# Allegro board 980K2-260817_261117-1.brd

Outline 419.1 x 474.98 mm; copper layers: TOP, L02_GND, L03_DP, L04_GND, L05_DP, L06_GND, L07_VI, L08_GND, L09_VI, L10_GND, L11_VI, L12_GND, L13_VI, L14_GND, L15_5V, L16_5V, L17_C-BIT, L18_C-BIT, L19_GND, L20_VI, L21_GND, L22_VI, L23_GND, L24_VI, L25_GND, L26_VI, L27_GND, L28_DP, L29_GND, L30_DP, L31_GND, BOTTOM. Coordinates in mm from the lower left corner of the outline.

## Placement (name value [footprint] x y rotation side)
BC9  0.1U-50-X-S4-TDK  [C0402]  86.11 107.82 180 bottom
BR5  1K-1-S4  [R0402]  86.11 106.3 0 bottom
BR6  1K-1-S4  [R0402]  86.11 103.5 0 bottom
BR7  0-5-S6  [R0603]  83.44 106.3 180 bottom
BR8  0-5-S4  [R0402]  86.11 105.03 180 bottom
BR9  0-5-S4  [R0402]  86.11 102.24 180 bottom
BU1  AT24C512C-SSHM-T-SOIC8  [SO8_206X127MM]  91.06 105.66 180 bottom
C48  0.01U-100-X7R-S6-MU  [C0603]  147.57 273.87 90 bottom
C49  0.01U-100-X7R-S6-MU  [C0603]  136.27 268.99 270 bottom
C50  0.01U-100-X7R-S6-MU  [C0603]  142.28 268.54 270 bottom
C53  1U-16-X5R-S4-YA  [C0402]  142.24 261.62 270 bottom
C54  2.2U-16-X-S4-MU  [C0402]  136.53 261.62 270 bottom
C58  1U-16-X5R-S4-YA  [C0402]  142.11 257.68 270 bottom
C59  4.7U-100-X-SB-MU  [C1210]  140.59 246.51 270 bottom
C60  0.01U-100-X7R-S6-MU  [C0603]  147.01 259.72 0 bottom
C61  0.01U-100-X7R-S6-MU  [C0603]  156.88 264.78 180 bottom
C62  2.2U-16-X-S4-MU  [C0402]  157.07 259.72 0 bottom
C63  0.01U-100-X7R-S6-MU  [C0603]  157.73 261.82 90 bottom
C64  0.01U-100-X7R-S6-MU  [C0603]  156.88 267.82 180 bottom
C65  0.1U-25-X7R-S4-MU  [C0402]  157.73 271.37 90 bottom
C66  0.1U-25-X7R-S4-MU  [C0402]  152.65 276.61 180 bottom
C67  0.1U-25-X7R-S4-MU  [C0402]  150.24 278.13 180 bottom
C68  0.1U-25-X7R-S4-MU  [C0402]  147.83 282.7 180 bottom
C69  0.01U-100-X7R-S6-MU  [C0603]  151.96 259.72 0 bottom
C70  0.1U-25-X7R-S4-MU  [C0402]  122.8 294.89 180 bottom
C71  0.1U-25-X7R-S4-MU  [C0402]  129.42 294.89 180 bottom
C72  0.1U-25-X7R-S4-MU  [C0402]  158.75 227.33 0 bottom
C73  0.1U-25-X7R-S4-MU  [C0402]  153.67 227.33 0 bottom
C74  0.1U-25-X7R-S4-MU  [C0402]  157.73 273.91 90 bottom
CT1  47U-16-X5R-SB-MU  [C1210]  88.14 153.16 180 bottom
CT2  10U-16-X5R-S8-TY  [C0805]  108.2 164.59 90 bottom
CT3  22U-16-X-S8-MU  [C0805]  110.49 164.59 90 bottom
CT7  47U-16-X5R-SB-MU  [C1210]  88.14 132.84 180 bottom
CT8  10U-16-X5R-S8-TY  [C0805]  110.49 144.27 90 bottom
CT9  22U-16-X-S8-MU  [C0805]  108.2 144.27 90 bottom
F1  C1F8-0.25A-SA  [FUSE_1206_H1P05MM]  88.14 156.72 0 bottom
F2  C1F8-0.25A-SA  [FUSE_1206_H1P05MM]  88.14 136.4 0 bottom
FD1  -  [FD_040_V2]  95.25 123.19 0 top
FD2  -  [FD_040_V2]  323.85 123.19 0 top
FD3  -  [FD_040_V2]  323.85 351.79 0 top
FD4  -  [FD_040_V2]  95.25 351.79 0 top
FD5  -  [FD_040_V2]  323.85 123.19 180 bottom
FD6  -  [FD_040_V2]  95.25 123.19 180 bottom
FD7  -  [FD_040_V2]  95.25 351.79 180 bottom
FD8  -  [FD_040_V2]  323.85 351.79 180 bottom
FD9  -  [FD_040_V2]  19.05 123.19 0 top
FD10  -  [FD_040_V2]  400.05 123.19 0 top
FD11  -  [FD_040_V2]  400.05 351.79 0 top
FD12  -  [FD_040_V2]  19.05 351.79 0 top
FD13  -  [FD_040_V2]  400.05 123.19 180 bottom
FD14  -  [FD_040_V2]  19.05 123.19 180 bottom
FD15  -  [FD_040_V2]  19.05 351.79 180 bottom
FD16  -  [FD_040_V2]  400.05 351.79 180 bottom
K1  UA2-5NJ-A-V3  [RL_NECUA2_5V_V3]  138.43 290.63 270 bottom
K2  G3VM-201DR  [RL_G3VM201DR_200V]  144.15 277.5 0 bottom
K3  G3VM-201DR  [RL_G3VM201DR_200V]  134.49 273.18 90 bottom
K4  G3VM-201DR  [RL_G3VM201DR_200V]  144.15 291.47 0 bottom
K5  G3VM-51UR-5V-VSON4  [RL_G3VM_4P_VSON4]  139.95 268.99 0 bottom
K6  G3VM-51UR-5V-VSON4  [RL_G3VM_4P_VSON4]  139.95 266.19 0 bottom
K7  G3VM-51UR-5V-VSON4  [RL_G3VM_4P_VSON4]  139.95 264.16 0 bottom
K8  G3VM-51UR-5V-VSON4  [RL_G3VM_4P_VSON4]  139.95 261.62 0 bottom
K9  G3VM-51UR-5V-VSON4  [RL_G3VM_4P_VSON4]  134.24 261.62 0 bottom
K10  G3VM-51UR-5V-VSON4  [RL_G3VM_4P_VSON4]  135.38 264.16 0 bottom
K11  G3VM-51UR-5V-VSON4  [RL_G3VM_4P_VSON4]  143.76 257.3 90 bottom
K12  G3VM-51UR-5V-VSON4  [RL_G3VM_4P_VSON4]  143.76 252.48 90 bottom
K13  G3VM-51UR-5V-VSON4  [RL_G3VM_4P_VSON4]  143.76 246.51 90 bottom
K14  G3VM-51UR-5V-VSON4  [RL_G3VM_4P_VSON4]  146.56 252.48 90 bottom
K15  UA2-5NJ-A-V3  [RL_NECUA2_5V_V3]  135.25 242.75 270 bottom
K16  G3VM-51UR-5V-VSON4  [RL_G3VM_4P_VSON4]  146.56 257.3 90 bottom
K17  G3VM-51UR-5V-VSON4  [RL_G3VM_4P_VSON4]  148.72 257.3 90 bottom
K18  G3VM-51UR-5V-VSON4  [RL_G3VM_4P_VSON4]  148.72 252.48 90 bottom
K19  G3VM-51UR-5V-VSON4  [RL_G3VM_4P_VSON4]  151.51 257.3 90 bottom
K20  G3VM-51UR-5V-VSON4  [RL_G3VM_4P_VSON4]  151.51 252.48 90 bottom
K21  G3VM-51UR-5V-VSON4  [RL_G3VM_4P_VSON4]  153.67 257.3 90 bottom
K22  G3VM-51UR-5V-VSON4  [RL_G3VM_4P_VSON4]  153.67 252.48 90 bottom
K23  UA2-5NJ-A-V3  [RL_NECUA2_5V_V3]  152.78 242.75 270 bottom
K24  UA2-5NJ-A-V3  [RL_NECUA2_5V_V3]  161.04 242.75 270 bottom
K25  G3VM-51UR-5V-VSON4  [RL_G3VM_4P_VSON4]  156.97 257.3 90 bottom
K26  G3VM-51UR-5V-VSON4  [RL_G3VM_4P_VSON4]  156.97 252.48 90 bottom
K27  G3VM-51UR-5V-VSON4  [RL_G3VM_4P_VSON4]  160.15 261.37 180 bottom
K28  G3VM-51UR-5V-VSON4  [RL_G3VM_4P_VSON4]  164.72 261.37 180 bottom
K29  G3VM-51UR-5V-VSON4  [RL_G3VM_4P_VSON4]  169.29 261.37 180 bottom
K30  G3VM-51UR-5V-VSON4  [RL_G3VM_4P_VSON4]  160.15 265.18 180 bottom
K31  G3VM-51UR-5V-VSON4  [RL_G3VM_4P_VSON4]  164.72 265.18 180 bottom
K32  G3VM-51UR-5V-VSON4  [RL_G3VM_4P_VSON4]  169.29 265.18 180 bottom
K33  G3VM-51UR-5V-VSON4  [RL_G3VM_4P_VSON4]  160.15 268.22 180 bottom
K34  G3VM-51UR-5V-VSON4  [RL_G3VM_4P_VSON4]  164.72 268.22 180 bottom
K35  G3VM-51UR-5V-VSON4  [RL_G3VM_4P_VSON4]  169.29 268.22 180 bottom
K36  G3VM-51UR-5V-VSON4  [RL_G3VM_4P_VSON4]  160.15 271.27 180 bottom
K37  G3VM-51UR-5V-VSON4  [RL_G3VM_4P_VSON4]  164.72 271.27 180 bottom
K38  G3VM-51UR-5V-VSON4  [RL_G3VM_4P_VSON4]  160.15 273.81 180 bottom
K39  G3VM-51UR-5V-VSON4  [RL_G3VM_4P_VSON4]  164.72 273.81 180 bottom
K40  G3VM-51UR-5V-VSON4  [RL_G3VM_4P_VSON4]  155.58 273.05 270 bottom
K41  G3VM-51UR-5V-VSON4  [RL_G3VM_4P_VSON4]  155.58 277.62 270 bottom
K42  G3VM-51UR-5V-VSON4  [RL_G3VM_4P_VSON4]  155.58 282.19 270 bottom
K43  G3VM-51UR-5V-VSON4  [RL_G3VM_4P_VSON4]  152.65 273.05 270 bottom
K44  G3VM-51UR-5V-VSON4  [RL_G3VM_4P_VSON4]  152.65 278.89 270 bottom
K45  G3VM-51UR-5V-VSON4  [RL_G3VM_4P_VSON4]  152.65 283.46 270 bottom
K46  G3VM-51UR-5V-VSON4  [RL_G3VM_4P_VSON4]  150.24 274.57 270 bottom
K47  G3VM-51UR-5V-VSON4  [RL_G3VM_4P_VSON4]  150.24 280.42 270 bottom
K48  G3VM-51UR-5V-VSON4  [RL_G3VM_4P_VSON4]  150.24 284.99 270 bottom
K49  G3VM-51UR-5V-VSON4  [RL_G3VM_4P_VSON4]  147.83 284.99 270 bottom
K50  G3VM-51UR-5V-VSON4  [RL_G3VM_4P_VSON4]  147.83 279.15 270 bottom
K51  G3VM-51UR-5V-VSON4  [RL_G3VM_4P_VSON4]  148.72 246.51 270 bottom
K52  G3VM-51UR-5V-VSON4  [RL_G3VM_4P_VSON4]  148.72 241.17 90 bottom
K53  G3VM-51UR-5V-VSON4  [RL_G3VM_4P_VSON4]  156.97 246.51 270 bottom
K54  G3VM-51UR-5V-VSON4  [RL_G3VM_4P_VSON4]  156.97 241.17 90 bottom
K55  G3VM-51UR-5V-VSON4  [RL_G3VM_4P_VSON4]  123.44 292.35 0 bottom
K56  G3VM-201DR  [RL_G3VM201DR_200V]  128.4 288.67 90 bottom
K57  G3VM-51UR-5V-VSON4  [RL_G3VM_4P_VSON4]  158.12 234.57 270 bottom
K58  G3VM-51UR-5V-VSON4  [RL_G3VM_4P_VSON4]  156.08 234.57 270 bottom
K59  G3VM-51UR-5V-VSON4  [RL_G3VM_4P_VSON4]  153.04 234.57 270 bottom
K60  G3VM-51UR-5V-VSON4  [RL_G3VM_4P_VSON4]  151 234.57 270 bottom
K61  G3VM-51UR-5V-VSON4  [RL_G3VM_4P_VSON4]  130.05 292.35 0 bottom
LD1  LDG-2-S6  [LED_0603]  88.91 165.19 0 top
LD3  LDG-2-S6  [LED_0603]  88.91 144.87 0 top
LT1  L10U-16A-S16.5X15.5-PU  [IND_16P5X15P5MM]  98.93 156.59 0 bottom
LT3  L10U-16A-S16.5X15.5-PU  [IND_16P5X15P5MM]  98.93 136.27 0 bottom
M1  PG_LTXDX_F_X1_OUTLINE_TD_V2  [PG_LTXDX_F_X1_OUTLINE_TD_COHU]  209.55 237.49 0 top
NOREF  -  []  264.16 196.43 90 top
NOREF#2  -  []  174.43 232.23 0 top
NOREF#3  -  []  228.81 250.88 90 top
NOREF#4  -  []  248.54 204.45 90 top
NOREF#5  -  []  281.75 212.22 0 top
NOREF#6  -  []  227.3 280.35 0 top
NOREF#7  -  []  283.84 274.21 0 top
NOREF#8  -  []  262.81 186.81 0 top
NOREF#9  -  []  196.8 285.06 90 top
NOREF#10  -  []  173.62 229.09 90 top
NOREF#11  -  []  208.42 264.78 90 top
NOREF#12  -  []  151.91 251.6 90 top
NOREF#13  -  []  171.65 233.3 90 top
NOREF#14  -  []  134.43 232.23 0 top
NOREF#15  -  []  153.18 282.26 90 top
NOREF#16  -  []  159.72 214.65 90 top
NOREF#17  -  []  204.95 207.27 90 top
NOREF#18  -  []  155.05 218.82 0 top
NOREF#19  -  []  106.83 127.87 90 top
NOREF#20  -  []  227.8 269.99 0 top
NOREF#21  -  []  143.61 396.29 0 top
NOREF#22  -  []  274.33 264.33 90 top
NOREF#23  -  []  226.01 244.91 90 top
NOREF#24  -  []  199.27 265.58 0 top
NOREF#25  -  []  271.95 238.07 0 top
NOREF#26  -  []  274.07 256.43 90 top
NOREF#27  -  []  159.27 273.41 90 top
NOREF#28  -  []  90.49 457.2 0 top
NOREF#29  -  []  220.83 265.79 90 top
NOREF#30  -  []  273.56 233.37 90 top
NOREF#31  -  []  270.77 223.79 90 top
NOREF#32  -  []  199.4 213.09 90 top
NOREF#33  -  []  218.35 207.01 0 top
NOREF#34  -  []  279.27 261.77 0 top
NOREF#35  -  []  148.32 198.18 0 top
NOREF#36  -  []  231.11 260.17 90 top
NOREF#37  -  []  261.55 209.94 90 top
NOREF#38  -  []  122.85 281.02 0 top
NOREF#39  -  []  178.85 181.15 90 top
NOREF#40  -  []  232.13 220.09 0 top
NOREF#41  -  []  272.72 257.6 0 top
NOREF#42  -  []  166.32 212.22 0 top
NOREF#43  -  []  224.16 191.6 90 top
NOREF#44  -  []  195.68 233.69 90 top
NOREF#45  -  []  232.25 218.02 90 top
NOREF#46  -  []  159.27 201.77 0 top
NOREF#47  -  []  152.46 252.5 90 top
NOREF#48  -  []  179.72 213.6 90 top
NOREF#49  -  []  235.17 212.18 0 top
NOREF#50  -  []  277.25 256.75 0 top
NOREF#51  -  []  200.23 236.17 90 top
NOREF#52  -  []  234.33 204.33 90 top
NOREF#53  -  []  124.61 294.24 90 top
NOREF#54  -  []  232.66 226.35 90 top
NOREF#55  -  []  170.02 214.45 0 top
NOREF#56  -  []  223.49 257.85 90 top
NOREF#57  -  []  265.41 286.99 90 top
NOREF#58  -  []  146.28 193.03 90 top
NOREF#59  -  []  193.27 253.35 0 top
NOREF#60  -  []  162.85 297.22 0 top
NOREF#61  -  []  151.53 173.37 90 top
NOREF#62  -  []  239.27 274.21 0 top
NOREF#63  -  []  257.29 247.78 0 top
NOREF#64  -  []  176.38 264.09 90 top
NOREF#65  -  []  195.05 214.25 0 top
NOREF#66  -  []  236.81 232.54 0 top
NOREF#67  -  []  152.13 274.25 0 top
NOREF#68  -  []  276.38 241.15 90 top
NOREF#69  -  []  229.84 273.7 90 top
NOREF#70  -  []  236.1 271.85 90 top
NOREF#71  -  []  151.95 238.07 0 top
NOREF#72  -  []  243.92 229.94 0 top
NOREF#73  -  []  178.95 266.12 0 top
NOREF#74  -  []  276.79 171.3 0 top
NOREF#75  -  []  201.75 266.13 0 top
NOREF#76  -  []  243.97 260.64 90 top
NOREF#77  -  []  238.91 232.21 90 top
NOREF#78  -  []  219.08 205.79 0 top
NOREF#79  -  []  187.43 224.11 90 top
NOREF#80  -  []  139.08 203.76 0 top
NOREF#81  -  []  286.32 272.22 0 top
NOREF#82  -  []  276.61 233.37 90 top
NOREF#83  -  []  195.68 233.69 0 top
NOREF#84  -  []  244.44 292.28 90 top
NOREF#85  -  []  270.97 190.88 90 top
NOREF#86  -  []  178.35 207.01 0 top
NOREF#87  -  []  239.4 262.09 0 top
NOREF#88  -  []  152.25 212.18 0 top
NOREF#89  -  []  178.35 269.04 0 top
NOREF#90  -  []  157.04 244.35 0 top
NOREF#91  -  []  149.12 256.43 90 top
NOREF#92  -  []  236.1 220.99 90 top
NOREF#93  -  []  248.42 261.77 0 top
NOREF#94  -  []  279.4 205.9 0 top
NOREF#95  -  []  222.81 246.81 0 top
NOREF#96  -  []  279.72 214.65 90 top
NOREF#97  -  []  215.24 201.55 90 top
NOREF#98  -  []  235.68 173.69 90 top
NOREF#99  -  []  144.71 241.71 90 top
NOREF#100  -  []  216.63 232.23 0 top
NOREF#101  -  []  169.52 267.27 90 top
NOREF#102  -  []  220.95 264.09 90 top
NOREF#103  -  []  243.84 267.82 90 top
NOREF#104  -  []  272.63 173.69 90 top
NOREF#105  -  []  151.11 258.18 0 top
NOREF#106  -  []  294.09 264.23 90 top
NOREF#107  -  []  157.18 176.17 90 top
NOREF#108  -  []  175.84 202.57 90 top
NOREF#109  -  []  192.25 278.02 90 top
NOREF#110  -  []  227.8 264.99 90 top
NOREF#111  -  []  208.42 267.82 90 top
NOREF#112  -  []  156.84 167.33 0 top
NOREF#113  -  []  288.42 264.78 90 top
NOREF#114  -  []  264.16 185.63 90 top
NOREF#115  -  []  152.63 233.69 0 top
NOREF#116  -  []  261.59 308.11 0 top
NOREF#117  -  []  283.97 207.5 90 top
NOREF#118  -  []  181.55 269.94 90 top
NOREF#119  -  []  279.06 238.07 0 top
NOREF#120  -  []  263.49 193.03 90 top
NOREF#121  -  []  232.87 248.11 90 top
NOREF#122  -  []  240.13 456.29 90 top
NOREF#123  -  []  235.15 236.17 90 top
NOREF#124  -  []  174.04 210.63 90 top
NOREF#125  -  []  148.32 258.18 0 top
NOREF#126  -  []  233.27 258.18 0 top
NOREF#127  -  []  266.69 283.04 90 top
NOREF#128  -  []  223.49 193.03 90 top
NOREF#129  -  []  208.42 208.62 0 top
NOREF#130  -  []  136.28 307.18 0 top
NOREF#131  -  []  199.4 264.45 90 top
NOREF#132  -  []  123.92 229.94 0 top
NOREF#133  -  []  88.44 105.03 90 top
NOREF#134  -  []  88.14 130.81 90 top
NOREF#135  -  []  173.24 261.55 0 top
NOREF#136  -  []  275.17 212.18 90 top
NOREF#137  -  []  209.49 220.89 0 top
NOREF#138  -  []  203.97 213.09 90 top
NOREF#139  -  []  281.75 269.17 0 top
NOREF#140  -  []  181.6 308.11 0 top
NOREF#141  -  []  210.89 209.17 0 top
NOREF#142  -  []  286.32 262.32 0 top
NOREF#143  -  []  191.76 227.33 0 top
NOREF#144  -  []  198.64 173.37 90 top
NOREF#145  -  []  155.05 283.39 0 top
NOREF#146  -  []  173.34 17.15 0 top
NOREF#147  -  []  261.55 269.94 90 top
NOREF#148  -  []  220.83 205.79 90 top
NOREF#149  -  []  153.03 232.1 0 top
NOREF#150  -  []  146.17 286.14 90 top
NOREF#151  -  []  249.17 231.95 0 top
NOREF#152  -  []  155.68 233.69 90 top
NOREF#153  -  []  199.27 268.62 0 top
NOREF#154  -  []  196.57 245.63 0 top
NOREF#155  -  []  221.55 262.57 90 top
NOREF#156  -  []  151.24 197.85 90 top
NOREF#157  -  []  149.24 185.31 90 top
NOREF#158  -  []  221.59 294.14 0 top
NOREF#159  -  []  288.42 207.82 90 top
NOREF#160  -  []  163.97 268.95 0 top
NOREF#161  -  []  268.99 196.75 0 top
NOREF#162  -  []  151.91 256.43 90 top
NOREF#163  -  []  145.61 192.78 0 top
NOREF#164  -  []  279.27 273.41 90 top
NOREF#165  -  []  231.18 179.15 0 top
NOREF#166  -  []  188.32 185.63 90 top
NOREF#167  -  []  276.1 280.99 90 top
NOREF#168  -  []  154.07 191.6 90 top
NOREF#169  -  []  211.14 458.49 0 top
NOREF#170  -  []  192.25 272.17 90 top
NOREF#171  -  []  148.32 182.05 0 top
NOREF#172  -  []  232.63 173.69 90 top
NOREF#173  -  []  154.62 252.5 90 top
NOREF#174  -  []  151.24 193.03 90 top
NOREF#175  -  []  286.32 269.17 0 top
NOREF#176  -  []  199.27 274.21 0 top
NOREF#177  -  []  203.84 261.77 0 top
NOREF#178  -  []  139.55 234.49 0 top
NOREF#179  -  []  210.89 266.13 0 top
NOREF#180  -  []  260.83 268.59 90 top
NOREF#181  -  []  150.41 228.7 90 top
NOREF#182  -  []  196.84 167.33 0 top
NOREF#183  -  []  281.75 209.17 0 top
NOREF#184  -  []  251.05 245.49 90 top
NOREF#185  -  []  258.35 271.84 0 top
NOREF#186  -  []  214.51 263.76 0 top
NOREF#187  -  []  187.8 209.99 0 top
NOREF#188  -  []  216.55 254.49 90 top
NOREF#189  -  []  236.02 192.78 0 top
NOREF#190  -  []  266.96 196.43 90 top
NOREF#191  -  []  237.25 196.75 0 top
NOREF#192  -  []  185.41 273.02 90 top
NOREF#193  -  []  159.72 223.79 90 top
NOREF#194  -  []  199.27 261.77 0 top
NOREF#195  -  []  149.67 190.01 0 top
NOREF#196  -  []  231.79 191.93 0 top
NOREF#197  -  []  159.06 178.07 0 top
NOREF#198  -  []  159.65 272.56 0 top
NOREF#199  -  []  196.52 216.55 0 top
NOREF#200  -  []  156.1 276.42 90 top
NOREF#201  -  []  236.02 197.6 0 top
NOREF#202  -  []  281.75 266.13 0 top
NOREF#203  -  []  136.55 220.49 0 top
NOREF#204  -  []  237.18 176.17 90 top
NOREF#205  -  []  181.6 234.15 0 top
NOREF#206  -  []  276.1 276.42 90 top
NOREF#207  -  []  275.56 175.77 0 top
NOREF#208  -  []  275.96 168.6 90 top
NOREF#209  -  []  226.96 251.6 90 top
NOREF#210  -  []  199.72 274.65 90 top
NOREF#211  -  []  232.25 272.17 90 top
NOREF#212  -  []  279.44 239.15 0 top
NOREF#213  -  []  124.61 234.89 90 top
NOREF#214  -  []  293.99 17.15 90 top
NOREF#215  -  []  196.38 241.15 90 top
NOREF#216  -  []  129.44 260.67 90 top
NOREF#217  -  []  191.11 253.35 0 top
NOREF#218  -  []  279.27 213.41 90 top
NOREF#219  -  []  243.84 274.21 0 top
NOREF#220  -  []  154.84 18.69 90 top
NOREF#221  -  []  283.97 212 0 top
NOREF#222  -  []  161.75 214.76 0 top
NOREF#223  -  []  228.32 245.63 90 top
NOREF#224  -  []  276.57 185.63 90 top
NOREF#225  -  []  220.95 266.12 90 top
NOREF#226  -  []  148.44 193.03 90 top
NOREF#227  -  []  214.43 232.23 0 top
NOREF#228  -  []  197.04 184.35 0 top
NOREF#229  -  []  178.85 241.15 90 top
NOREF#230  -  []  231.91 191.6 90 top
NOREF#231  -  []  236.79 171.3 0 top
NOREF#232  -  []  153.56 233.37 90 top
NOREF#233  -  []  284.64 241.15 90 top
NOREF#234  -  []  157.25 240.62 0 top
NOREF#235  -  []  244.32 231.95 90 top
NOREF#236  -  []  279.27 214.21 0 top
NOREF#237  -  []  211.05 229.49 0 top
NOREF#238  -  []  149.55 318.49 0 top
NOREF#239  -  []  180.83 265.79 90 top
NOREF#240  -  []  271.71 231.3 0 top
NOREF#241  -  []  189.12 191.6 90 top
NOREF#242  -  []  169.52 212.86 90 top
NOREF#243  -  []  233.76 255.7 90 top
NOREF#244  -  []  147.8 264.99 90 top
NOREF#245  -  []  237.37 196.43 90 top
NOREF#246  -  []  275.92 250.88 90 top
NOREF#247  -  []  267.77 181.47 0 top
NOREF#248  -  []  143.36 247.38 0 top
NOREF#249  -  []  159.4 273.09 90 top
NOREF#250  -  []  147.45 209.24 0 top
NOREF#251  -  []  199.27 207.82 90 top
NOREF#252  -  []  196.1 280.99 90 top
NOREF#253  -  []  241.44 244.35 0 top
NOREF#254  -  []  256.55 254.49 90 top
NOREF#255  -  []  168.54 200.64 90 top
NOREF#256  -  []  276.57 198.18 0 top
NOREF#257  -  []  118.64 291.4 90 top
NOREF#258  -  []  181.03 267.69 90 top
NOREF#259  -  []  160.23 236.17 90 top
NOREF#260  -  []  197.74 226.35 90 top
NOREF#261  -  []  183.36 258.18 0 top
NOREF#262  -  []  194.39 286.59 90 top
NOREF#263  -  []  200.23 176.17 90 top
NOREF#264  -  []  236.8 220.49 90 top
NOREF#265  -  []  279.72 279.22 90 top
NOREF#266  -  []  279.4 270.55 90 top
NOREF#267  -  []  163.97 200.64 90 top
NOREF#268  -  []  149.55 188.99 90 top
NOREF#269  -  []  213.24 201.55 0 top
NOREF#270  -  []  276.81 172.54 0 top
NOREF#271  -  []  156.1 216.42 90 top
NOREF#272  -  []  186.16 193.35 0 top
NOREF#273  -  []  178.97 18.69 90 top
NOREF#274  -  []  256.38 204.09 90 top
NOREF#275  -  []  270.15 206.89 90 top
NOREF#276  -  []  88.16 144.87 0 top
NOREF#277  -  []  123.91 295.42 90 top
NOREF#278  -  []  232.25 278.02 0 top
NOREF#279  -  []  261.03 267.69 90 top
NOREF#280  -  []  187.9 265.84 90 top
NOREF#281  -  []  168.45 235.2 0 top
NOREF#282  -  []  272.13 280.09 0 top
NOREF#283  -  []  159.27 211.67 0 top
NOREF#284  -  []  241.12 248.11 90 top
NOREF#285  -  []  201.41 167.9 90 top
NOREF#286  -  []  261.55 202.57 90 top
NOREF#287  -  []  259.39 16.49 0 top
NOREF#288  -  []  155.05 214.25 0 top
NOREF#289  -  []  288.54 267.5 90 top
NOREF#290  -  []  88.16 165.19 0 top
NOREF#291  -  []  280.23 236.17 90 top
NOREF#292  -  []  229.84 273.7 0 top
NOREF#293  -  []  199.65 212.56 0 top
NOREF#294  -  []  85.59 135.25 90 top
NOREF#295  -  []  216.63 292.23 0 top
NOREF#296  -  []  267.43 218.27 90 top
NOREF#297  -  []  209.52 260.42 90 top
NOREF#298  -  []  174.43 292.23 0 top
NOREF#299  -  []  188.32 198.18 0 top
NOREF#300  -  []  203.84 267.82 90 top
NOREF#301  -  []  289.52 272.86 90 top
NOREF#302  -  []  229.72 215.77 0 top
NOREF#303  -  []  279.27 208.62 0 top
NOREF#304  -  []  221.55 202.57 90 top
NOREF#305  -  []  163.84 214.21 0 top
NOREF#306  -  []  233.94 256.75 0 top
NOREF#307  -  []  231.91 196.43 90 top
NOREF#308  -  []  270.98 184.35 0 top
NOREF#309  -  []  151.79 196.75 0 top
NOREF#310  -  []  281.75 214.76 0 top
NOREF#311  -  []  318.12 17.15 0 top
NOREF#312  -  []  226.43 236.47 90 top
NOREF#313  -  []  156.52 216.55 0 top
NOREF#314  -  []  259.08 268.59 0 top
NOREF#315  -  []  188.32 253.35 0 top
NOREF#316  -  []  199.27 271.67 0 top
NOREF#317  -  []  143.36 187.38 0 top
NOREF#318  -  []  152.72 197.6 0 top
NOREF#319  -  []  148.35 217.95 90 top
NOREF#320  -  []  149.12 180.3 90 top
NOREF#321  -  []  270.56 257.6 0 top
NOREF#322  -  []  220.59 184.98 90 top
NOREF#323  -  []  226.7 237.02 90 top
NOREF#324  -  []  255.65 184.35 0 top
NOREF#325  -  []  193.56 173.37 90 top
NOREF#326  -  []  268.35 283.79 90 top
NOREF#327  -  []  147.8 269.99 0 top
NOREF#328  -  []  133.62 229.09 90 top
NOREF#329  -  []  151.11 198.18 0 top
NOREF#330  -  []  163.84 271.67 0 top
NOREF#331  -  []  198.64 233.37 90 top
NOREF#332  -  []  208.94 221.73 0 top
NOREF#333  -  []  211.05 185.49 90 top
NOREF#334  -  []  181.94 389.27 90 top
NOREF#335  -  []  139.55 240.49 90 top
NOREF#336  -  []  194.07 191.6 90 top
NOREF#337  -  []  238.11 172.1 0 top
NOREF#338  -  []  249.52 267.27 90 top
NOREF#339  -  []  269.72 221.62 0 top
NOREF#340  -  []  264.26 396.29 0 top
NOREF#341  -  []  151.98 226.59 90 top
NOREF#342  -  []  243.97 213.09 90 top
NOREF#343  -  []  254.09 200.42 90 top
NOREF#344  -  []  157.04 244.35 0 top
NOREF#345  -  []  146.7 237.02 90 top
NOREF#346  -  []  157.92 236.37 90 top
NOREF#347  -  []  180.43 284.38 90 top
NOREF#348  -  []  268.44 193.03 90 top
NOREF#349  -  []  196.57 198.18 0 top
NOREF#350  -  []  163.97 204.45 90 top
NOREF#351  -  []  195.15 176.17 90 top
NOREF#352  -  []  149.84 284.11 90 top
NOREF#353  -  []  195.92 195.7 90 top
NOREF#354  -  []  179.08 208.59 0 top
NOREF#355  -  []  191.85 18.69 0 top
NOREF#356  -  []  266.16 253.35 0 top
NOREF#357  -  []  236.02 252.78 0 top
NOREF#358  -  []  123.4 281.8 0 top
NOREF#359  -  []  266.69 297.01 90 top
NOREF#360  -  []  151.71 231.3 0 top
NOREF#361  -  []  271.98 280.75 90 top
NOREF#362  -  []  277.04 244.35 0 top
NOREF#363  -  []  268.32 253.35 0 top
NOREF#364  -  []  199.27 200.97 90 top
NOREF#365  -  []  145.42 213.02 90 top
NOREF#366  -  []  276.8 220.49 90 top
NOREF#367  -  []  180.95 204.09 90 top
NOREF#368  -  []  135.15 260.67 0 top
NOREF#369  -  []  274.78 236.5 90 top
NOREF#370  -  []  164.32 291.95 90 top
NOREF#371  -  []  190.97 239.57 90 top
NOREF#372  -  []  249.05 292.28 0 top
NOREF#373  -  []  189.72 286.19 0 top
NOREF#374  -  []  267.45 269.24 0 top
NOREF#375  -  []  189.84 219.54 0 top
NOREF#376  -  []  227.03 231.4 0 top
NOREF#377  -  []  233.18 211.85 90 top
NOREF#378  -  []  91.03 148.19 0 top
NOREF#379  -  []  149.84 219.54 0 top
NOREF#380  -  []  147.03 231.4 0 top
NOREF#381  -  []  148.32 245.63 90 top
NOREF#382  -  []  257.29 187.78 0 top
NOREF#383  -  []  190.56 192.78 0 top
NOREF#384  -  []  224.04 251.93 0 top
NOREF#385  -  []  235.96 228.6 90 top
NOREF#386  -  []  231.95 178.07 0 top
NOREF#387  -  []  270.98 244.35 0 top
NOREF#388  -  []  136.83 227.03 0 top
NOREF#389  -  []  159.24 184.35 0 top
NOREF#390  -  []  236.1 216.42 90 top
NOREF#391  -  []  243.84 270.87 90 top
NOREF#392  -  []  152.63 233.69 90 top
NOREF#393  -  []  247.04 299.09 0 top
NOREF#394  -  []  269.12 180.3 90 top
NOREF#395  -  []  91.03 127.87 0 top
NOREF#396  -  []  290.89 209.17 0 top
NOREF#397  -  []  237.5 185.31 90 top
NOREF#398  -  []  146.16 258.18 0 top
NOREF#399  -  []  186.01 255.7 90 top
NOREF#400  -  []  156.1 280.99 90 top
NOREF#401  -  []  220.83 261.22 90 top
NOREF#402  -  []  155.96 228.6 90 top
NOREF#403  -  []  241.75 212.22 0 top
NOREF#404  -  []  149.29 279.37 0 top
NOREF#405  -  []  128.45 235.2 0 top
NOREF#406  -  []  149.55 248.99 90 top
NOREF#407  -  []  264.16 191.6 90 top
NOREF#408  -  []  253.64 299.09 0 top
NOREF#409  -  []  174.51 263.76 0 top
NOREF#410  -  []  201.44 184.35 0 top
NOREF#411  -  []  191.91 196.43 90 top
NOREF#412  -  []  228.35 277.95 90 top
NOREF#413  -  []  239.4 205.9 0 top
NOREF#414  -  []  248.42 267.82 90 top
NOREF#415  -  []  279.27 210.87 90 top
NOREF#416  -  []  231.91 251.6 90 top
NOREF#417  -  []  228.44 241.72 90 top
NOREF#418  -  []  187.77 192.78 0 top
NOREF#419  -  []  183.36 247.38 0 top
NOREF#420  -  []  196.5 392.33 90 top
NOREF#421  -  []  283.97 262.09 0 top
NOREF#422  -  []  203.97 265.9 0 top
NOREF#423  -  []  136.5 285.91 0 top
NOREF#424  -  []  174.38 264.09 0 top
NOREF#425  -  []  268.35 223.79 90 top
NOREF#426  -  []  224.04 256.75 0 top
NOREF#427  -  []  264.16 245.63 90 top
NOREF#428  -  []  192.72 257.6 0 top
NOREF#429  -  []  239.06 238.07 0 top
NOREF#430  -  []  231.79 256.75 0 top
NOREF#431  -  []  106.83 148.19 90 top
NOREF#432  -  []  288.54 260.64 90 top
NOREF#433  -  []  208.54 262.09 0 top
NOREF#434  -  []  156.57 185.63 0 top
NOREF#435  -  []  193.18 271.85 90 top
NOREF#436  -  []  223.36 187.38 0 top
NOREF#437  -  []  204.95 270.32 90 top
NOREF#438  -  []  279.4 274.54 0 top
NOREF#439  -  []  243.97 212 0 top
NOREF#440  -  []  245.73 17.15 90 top
NOREF#441  -  []  187.9 205.84 90 top
NOREF#442  -  []  239.27 273.41 90 top
NOREF#443  -  []  270.6 173.69 0 top
NOREF#444  -  []  197.04 244.35 0 top
NOREF#445  -  []  187.03 171.4 0 top
NOREF#446  -  []  180.83 208.59 90 top
NOREF#447  -  []  221.85 246.47 0 top
NOREF#448  -  []  288.39 456.29 0 top
NOREF#449  -  []  201.75 274.76 0 top
NOREF#450  -  []  283.84 200.97 90 top
NOREF#451  -  []  159.27 213.41 90 top
NOREF#452  -  []  275.05 223.39 0 top
NOREF#453  -  []  260.95 204.09 90 top
NOREF#454  -  []  206.32 206.13 0 top
NOREF#455  -  []  163.97 214.54 0 top
NOREF#456  -  []  269.55 188.99 90 top
NOREF#457  -  []  226.96 196.43 90 top
NOREF#458  -  []  226.43 296.46 90 top
NOREF#459  -  []  164.61 294.24 90 top
NOREF#460  -  []  195.92 250.88 90 top
NOREF#461  -  []  227.3 286.19 0 top
NOREF#462  -  []  151.95 178.07 0 top
NOREF#463  -  []  236.7 197.85 90 top
NOREF#464  -  []  100.95 17.15 90 top
NOREF#465  -  []  237.37 240.3 90 top
NOREF#466  -  []  228.32 198.18 0 top
NOREF#467  -  []  208.54 204.45 90 top
NOREF#468  -  []  242.2 238.35 0 top
NOREF#469  -  []  211.25 184.35 0 top
NOREF#470  -  []  199.72 219.22 90 top
NOREF#471  -  []  141.6 234.15 0 top
NOREF#472  -  []  211.21 234.24 90 top
NOREF#473  -  []  270.86 82.65 0 top
NOREF#474  -  []  148.32 242.05 0 top
NOREF#475  -  []  246.32 206.13 0 top
NOREF#476  -  []  271.95 178.07 0 top
NOREF#477  -  []  253.64 239.09 0 top
NOREF#478  -  []  142.88 213.02 0 top
NOREF#479  -  []  150.77 283.79 90 top
NOREF#480  -  []  228.35 223.79 90 top
NOREF#481  -  []  178.83 232.23 0 top
NOREF#482  -  []  199.44 239.15 0 top
NOREF#483  -  []  276.81 232.54 0 top
NOREF#484  -  []  218.35 204.47 0 top
NOREF#485  -  []  271.19 288.49 0 top
NOREF#486  -  []  188.78 228.49 0 top
NOREF#487  -  []  166.32 272.22 0 top
NOREF#488  -  []  232.63 232.86 0 top
NOREF#489  -  []  237.71 172.86 0 top
NOREF#490  -  []  271.98 226.59 90 top
NOREF#491  -  []  176.55 220.49 0 top
NOREF#492  -  []  266.16 198.18 0 top
NOREF#493  -  []  283.97 214.54 0 top
NOREF#494  -  []  235.05 278.82 0 top
NOREF#495  -  []  271.11 253.35 0 top
NOREF#496  -  []  184.16 191.6 90 top
NOREF#497  -  []  192.25 218.02 90 top
NOREF#498  -  []  276.54 227 0 top
NOREF#499  -  []  186.83 256.75 0 top
NOREF#500  -  []  271.98 220.75 90 top
NOREF#501  -  []  161.75 274.76 0 top
NOREF#502  -  []  187.3 286.19 0 top
NOREF#503  -  []  148.78 244.35 0 top
NOREF#504  -  []  134.51 203.76 0 top
NOREF#505  -  []  152.25 278.02 0 top
NOREF#506  -  []  193.03 232.1 0 top
NOREF#507  -  []  234.78 236.5 90 top
NOREF#508  -  []  156.7 241.72 90 top
NOREF#509  -  []  274.78 176.5 90 top
NOREF#510  -  []  140.95 208.91 90 top
NOREF#511  -  []  146.7 223.05 90 top
NOREF#512  -  []  186.16 258.18 0 top
NOREF#513  -  []  191.91 191.6 90 top
NOREF#514  -  []  189.72 215.77 0 top
NOREF#515  -  []  283.84 265.58 0 top
NOREF#516  -  []  138.35 207.01 0 top
NOREF#517  -  []  196.52 225.69 0 top
NOREF#518  -  []  237.37 251.6 90 top
NOREF#519  -  []  157.25 256.75 0 top
NOREF#520  -  []  168.45 295.2 0 top
NOREF#521  -  []  156.79 231.3 0 top
NOREF#522  -  []  186.16 260.17 90 top
NOREF#523  -  []  196.7 241.72 90 top
NOREF#524  -  []  262.81 246.81 0 top
NOREF#525  -  []  204.61 234.89 90 top
NOREF#526  -  []  131.05 229.49 0 top
NOREF#527  -  []  264.04 196.75 0 top
NOREF#528  -  []  237.04 184.35 0 top
NOREF#529  -  []  232.25 212.18 90 top
NOREF#530  -  []  233.39 193.03 90 top
NOREF#531  -  []  236.57 242.05 0 top
NOREF#532  -  []  269.72 286.19 0 top
NOREF#533  -  []  275.05 274.25 0 top
NOREF#534  -  []  164.44 292.28 90 top
NOREF#535  -  []  273.18 184.35 0 top
NOREF#536  -  []  264.26 456.29 0 top
NOREF#537  -  []  243.84 208.62 0 top
NOREF#538  -  []  267.03 231.4 0 top
NOREF#539  -  []  199.4 207.5 90 top
NOREF#540  -  []  233.03 172.1 0 top
NOREF#541  -  []  218.95 266.12 0 top
NOREF#542  -  []  153.39 193.03 90 top
NOREF#543  -  []  182.87 213.02 0 top
NOREF#544  -  []  188.99 180.62 0 top
NOREF#545  -  []  193.27 258.18 0 top
NOREF#546  -  []  197.92 190.01 0 top
NOREF#547  -  []  239.27 210.87 90 top
NOREF#548  -  []  168.42 204.78 90 top
NOREF#549  -  []  275.17 272.17 90 top
NOREF#550  -  []  166.32 206.13 0 top
NOREF#551  -  []  202.26 236.17 90 top
NOREF#552  -  []  237.37 180.3 90 top
NOREF#553  -  []  265.09 197.49 90 top
NOREF#554  -  []  202.85 297.22 0 top
NOREF#555  -  []  222.6 82.65 0 top
NOREF#556  -  []  312.52 456.29 0 top
NOREF#557  -  []  232.72 257.6 0 top
NOREF#558  -  []  189.84 213.7 0 top
NOREF#559  -  []  191.79 251.93 0 top
NOREF#560  -  []  252.55 250.49 90 top
NOREF#561  -  []  276.1 271.85 90 top
NOREF#562  -  []  244.95 270.32 90 top
NOREF#563  -  []  196.1 271.85 90 top
NOREF#564  -  []  151.73 232.54 0 top
NOREF#565  -  []  270.88 228.6 90 top
NOREF#566  -  []  174.51 203.76 0 top
NOREF#567  -  []  196.02 181.47 0 top
NOREF#568  -  []  192.63 172.86 0 top
NOREF#569  -  []  208.42 268.62 0 top
NOREF#570  -  []  278.11 172.1 0 top
NOREF#571  -  []  262.03 289.03 90 top
NOREF#572  -  []  178.35 267.01 0 top
NOREF#573  -  []  230.56 192.78 0 top
NOREF#574  -  []  194.39 216.17 90 top
NOREF#575  -  []  216.83 287.03 0 top
NOREF#576  -  []  230.97 179.57 90 top
NOREF#577  -  []  271.91 196.43 90 top
NOREF#578  -  []  252.55 190.49 90 top
NOREF#579  -  []  256.38 264.09 90 top
NOREF#580  -  []  271.79 251.93 0 top
NOREF#581  -  []  163.84 274.21 0 top
NOREF#582  -  []  142.81 247.68 0 top
NOREF#583  -  []  273.18 282.26 90 top
NOREF#584  -  []  149.72 215.77 0 top
NOREF#585  -  []  147.77 236.37 0 top
NOREF#586  -  []  213.62 229.09 90 top
NOREF#587  -  []  186.7 223.05 90 top
NOREF#588  -  []  162.85 237.22 0 top
NOREF#589  -  []  197.03 238.07 0 top
NOREF#590  -  []  209.55 237.49 0 top
NOREF#591  -  []  239.4 267.5 90 top
NOREF#592  -  []  195.17 272.17 0 top
NOREF#593  -  []  241.84 295.2 0 top
NOREF#594  -  []  165.49 452.29 90 top
NOREF#595  -  []  241.75 262.32 0 top
NOREF#596  -  []  237.03 238.07 0 top
NOREF#597  -  []  199.27 213.41 90 top
NOREF#598  -  []  135.15 268.04 90 top
NOREF#599  -  []  197.71 172.86 0 top
NOREF#600  -  []  146.17 212.17 90 top
NOREF#601  -  []  290.89 262.32 0 top
NOREF#602  -  []  229.12 196.43 90 top
NOREF#603  -  []  230.88 228.6 90 top
NOREF#604  -  []  199.4 205.9 0 top
NOREF#605  -  []  242.2 178.35 0 top
NOREF#606  -  []  147.51 250.88 90 top
NOREF#607  -  []  219.73 238.35 0 top
NOREF#608  -  []  202.2 178.35 0 top
NOREF#609  -  []  261.85 292.49 0 top
NOREF#610  -  []  199.22 190.88 90 top
NOREF#611  -  []  154.62 247.68 90 top
NOREF#612  -  []  189.12 196.43 90 top
NOREF#613  -  []  179.08 201.22 0 top
NOREF#614  -  []  124.11 392.33 90 top
NOREF#615  -  []  283.97 273.09 90 top
NOREF#616  -  []  163.84 261.77 0 top
NOREF#617  -  []  275.92 195.7 90 top
NOREF#618  -  []  145.42 226.99 90 top
NOREF#619  -  []  132.55 224.49 0 top
NOREF#620  -  []  283.84 264.78 90 top
NOREF#621  -  []  294.09 260.42 90 top
NOREF#622  -  []  146.83 196.75 0 top
NOREF#623  -  []  233.6 226.96 0 top
NOREF#624  -  []  188.95 266.89 0 top
NOREF#625  -  []  263.36 187.38 0 top
NOREF#626  -  []  188.78 282.65 0 top
NOREF#627  -  []  229.84 224.11 0 top
NOREF#628  -  []  225.42 214.72 90 top
NOREF#629  -  []  266.16 286.14 90 top
NOREF#630  -  []  176.55 280.49 0 top
NOREF#631  -  []  146.16 198.18 0 top
NOREF#632  -  []  302.26 14.59 90 top
NOREF#633  -  []  236.57 198.18 0 top
NOREF#634  -  []  193.39 197.85 90 top
NOREF#635  -  []  214.09 200.42 90 top
NOREF#636  -  []  231.19 288.49 0 top
NOREF#637  -  []  191.18 239.15 0 top
NOREF#638  -  []  188.99 240.62 0 top
NOREF#639  -  []  281.12 188.11 90 top
NOREF#640  -  []  152.72 247.68 0 top
NOREF#641  -  []  235.92 195.7 90 top
NOREF#642  -  []  227.43 278.27 90 top
NOREF#643  -  []  265.09 257.49 90 top
NOREF#644  -  []  191.19 218.07 0 top
NOREF#645  -  []  194.33 207.37 90 top
NOREF#646  -  []  150.97 179.57 90 top
NOREF#647  -  []  275.05 283.39 0 top
NOREF#648  -  []  219.55 240.49 90 top
NOREF#649  -  []  167.74 396.29 0 top
NOREF#650  -  []  159.72 219.22 90 top
NOREF#651  -  []  196.7 253.03 90 top
NOREF#652  -  []  227.99 178.35 0 top
NOREF#653  -  []  246.32 269.17 0 top
NOREF#654  -  []  153.76 195.7 90 top
NOREF#655  -  []  236.52 281.12 0 top
NOREF#656  -  []  188.99 251.93 0 top
NOREF#657  -  []  188.44 257.85 90 top
NOREF#658  -  []  235.68 233.69 0 top
NOREF#659  -  []  192.25 222.59 0 top
NOREF#660  -  []  188.32 245.63 0 top
NOREF#661  -  []  286.32 209.17 0 top
NOREF#662  -  []  161.75 269.17 0 top
NOREF#663  -  []  149.72 286.19 0 top
NOREF#664  -  []  218.83 232.23 0 top
NOREF#665  -  []  208.54 200.64 90 top
NOREF#666  -  []  195.17 216.75 90 top
NOREF#667  -  []  213.65 179.15 0 top
NOREF#668  -  []  277.04 184.35 0 top
NOREF#669  -  []  168.54 264.45 90 top
NOREF#670  -  []  149.84 279.54 90 top
NOREF#671  -  []  89.74 155.92 0 top
NOREF#672  -  []  151.24 253.03 90 top
NOREF#673  -  []  282.26 176.17 90 top
NOREF#674  -  []  269.84 284.11 90 top
NOREF#675  -  []  124.44 292.28 90 top
NOREF#676  -  []  269.72 281.62 0 top
NOREF#677  -  []  145.61 254.08 0 top
NOREF#678  -  []  208.42 205.58 0 top
NOREF#679  -  []  248.42 268.62 0 top
NOREF#680  -  []  288.54 264.45 90 top
NOREF#681  -  []  262.87 213.02 0 top
NOREF#682  -  []  227.77 257.6 0 top
NOREF#683  -  []  206.32 266.13 0 top
NOREF#684  -  []  157.71 232.86 0 top
NOREF#685  -  []  199.4 260.64 90 top
NOREF#686  -  []  307.65 17.78 0 top
NOREF#687  -  []  268.99 180.62 0 top
NOREF#688  -  []  233.18 184.35 0 top
NOREF#689  -  []  190.48 235.77 0 top
NOREF#690  -  []  235.05 283.39 0 top
NOREF#691  -  []  182.81 197.6 0 top
NOREF#692  -  []  189.72 226.19 0 top
NOREF#693  -  []  197.92 250.01 0 top
NOREF#694  -  []  223.36 193.35 0 top
NOREF#695  -  []  266.83 191.93 0 top
NOREF#696  -  []  187.43 278.27 90 top
NOREF#697  -  []  234.39 282.02 90 top
NOREF#698  -  []  270.97 255.7 90 top
NOREF#699  -  []  256.26 263.76 90 top
NOREF#700  -  []  260.95 208.91 90 top
NOREF#701  -  []  229.84 213.7 0 top
NOREF#702  -  []  274.07 191.6 90 top
NOREF#703  -  []  225.41 213.02 90 top
NOREF#704  -  []  228.81 190.88 90 top
NOREF#705  -  []  159.4 202.09 0 top
NOREF#706  -  []  170.89 209.17 0 top
NOREF#707  -  []  164.95 270.32 90 top
NOREF#708  -  []  226.43 222.5 90 top
NOREF#709  -  []  193.18 244.35 0 top
NOREF#710  -  []  237.71 232.86 0 top
NOREF#711  -  []  255.02 208.14 90 top
NOREF#712  -  []  237.03 178.07 0 top
NOREF#713  -  []  177.29 247.78 0 top
NOREF#714  -  []  153.18 244.35 0 top
NOREF#715  -  []  269.12 196.43 90 top
NOREF#716  -  []  266.16 226.14 90 top
NOREF#717  -  []  276.02 197.6 0 top
NOREF#718  -  []  155.17 216.75 0 top
NOREF#719  -  []  201.75 272.22 0 top
NOREF#720  -  []  158.04 228.3 0 top
NOREF#721  -  []  239.24 184.35 0 top
NOREF#722  -  []  243.84 261.77 0 top
NOREF#723  -  []  274.39 276.17 90 top
NOREF#724  -  []  274.07 251.6 90 top
NOREF#725  -  []  159.22 195.7 90 top
NOREF#726  -  []  157.92 252.5 90 top
NOREF#727  -  []  218.97 271.91 90 top
NOREF#728  -  []  286.32 214.76 0 top
NOREF#729  -  []  223.89 245.24 90 top
NOREF#730  -  []  243.97 262.09 0 top
NOREF#731  -  []  142.81 241.71 0 top
NOREF#732  -  []  227.99 238.35 0 top
NOREF#733  -  []  248.54 268.95 0 top
NOREF#734  -  []  231.76 167.33 0 top
NOREF#735  -  []  193.95 196.75 0 top
NOREF#736  -  []  130.52 295.42 90 top
NOREF#737  -  []  151.24 257.85 90 top
NOREF#738  -  []  288.42 267.82 90 top
NOREF#739  -  []  180.95 206.12 90 top
NOREF#740  -  []  249.52 272.86 90 top
NOREF#741  -  []  205.38 226.23 0 top
NOREF#742  -  []  209.52 204.23 90 top
NOREF#743  -  []  272.72 252.78 0 top
NOREF#744  -  []  231.98 226.59 90 top
NOREF#745  -  []  243.97 272 0 top
NOREF#746  -  []  264.04 245.96 0 top
NOREF#747  -  []  148.32 253.35 0 top
NOREF#748  -  []  186.16 198.18 0 top
NOREF#749  -  []  233.27 193.35 0 top
NOREF#750  -  []  173.36 201.22 0 top
NOREF#751  -  []  203.4 296.38 0 top
NOREF#752  -  []  159.4 207.5 90 top
NOREF#753  -  []  275.68 233.69 0 top
NOREF#754  -  []  186.01 244.91 90 top
NOREF#755  -  []  251.05 229.49 0 top
NOREF#756  -  []  214.38 204.09 0 top
NOREF#757  -  []  283.84 205.58 0 top
NOREF#758  -  []  281.41 227.9 90 top
NOREF#759  -  []  190.73 19.69 90 top
NOREF#760  -  []  186.83 251.93 0 top
NOREF#761  -  []  148.81 195.7 90 top
NOREF#762  -  []  294.99 82.65 0 top
NOREF#763  -  []  138.97 211.91 90 top
NOREF#764  -  []  159.27 260.97 90 top
NOREF#765  -  []  195.17 276.75 90 top
NOREF#766  -  []  148.99 196.75 0 top
NOREF#767  -  []  289.52 267.27 90 top
NOREF#768  -  []  208.42 204.78 90 top
NOREF#769  -  []  236.8 285.06 90 top
NOREF#770  -  []  181.6 294.14 0 top
NOREF#771  -  []  152.25 218.02 90 top
NOREF#772  -  []  170.92 291.95 90 top
NOREF#773  -  []  199.4 268.95 0 top
NOREF#774  -  []  163.04 176.5 90 top
NOREF#775  -  []  197.47 17.15 0 top
NOREF#776  -  []  150.77 213.37 90 top
NOREF#777  -  []  209.52 264.23 90 top
NOREF#778  -  []  276.54 167 0 top
NOREF#779  -  []  201.75 212.22 0 top
NOREF#780  -  []  242.57 231.95 0 top
NOREF#781  -  []  185.61 197.6 0 top
NOREF#782  -  []  188.35 223.79 90 top
NOREF#783  -  []  243.97 205.9 0 top
NOREF#784  -  []  204.32 231.95 90 top
NOREF#785  -  []  186.96 251.6 90 top
NOREF#786  -  []  255.11 201.22 90 top
NOREF#787  -  []  235.17 276.75 90 top
NOREF#788  -  []  239.4 260.64 90 top
NOREF#789  -  []  239.65 272.56 0 top
NOREF#790  -  []  188.99 191.93 0 top
NOREF#791  -  []  283.97 268.95 0 top
NOREF#792  -  []  133.68 389.27 90 top
NOREF#793  -  []  156.02 252.5 0 top
NOREF#794  -  []  233.6 286.96 0 top
NOREF#795  -  []  203.97 210.55 90 top
NOREF#796  -  []  162.88 458.49 0 top
NOREF#797  -  []  157.25 191.93 0 top
NOREF#798  -  []  208.42 260.97 90 top
NOREF#799  -  []  208.45 295.2 0 top
NOREF#800  -  []  239.4 208.95 0 top
NOREF#801  -  []  241.41 227.9 90 top
NOREF#802  -  []  276.1 216.42 90 top
NOREF#803  -  []  278.64 233.37 90 top
NOREF#804  -  []  257.25 236.5 90 top
NOREF#805  -  []  163.84 208.62 0 top
NOREF#806  -  []  163.84 207.82 90 top
NOREF#807  -  []  193.6 282.39 0 top
NOREF#808  -  []  215.11 201.22 90 top
NOREF#809  -  []  155.56 175.77 0 top
NOREF#810  -  []  194.07 196.43 90 top
NOREF#811  -  []  283.97 272 0 top
NOREF#812  -  []  261.59 248.12 0 top
NOREF#813  -  []  151.53 233.37 90 top
NOREF#814  -  []  135.15 268.04 0 top
NOREF#815  -  []  94.87 108.59 0 top
NOREF#816  -  []  212.55 284.49 0 top
NOREF#817  -  []  184.04 185.96 0 top
NOREF#818  -  []  269.84 219.54 90 top
NOREF#819  -  []  273.26 456.29 0 top
NOREF#820  -  []  219.72 273.6 90 top
NOREF#821  -  []  221.59 234.15 0 top
NOREF#822  -  []  139.08 261.22 0 top
NOREF#823  -  []  151.7 285.06 90 top
NOREF#824  -  []  155.17 281.32 90 top
NOREF#825  -  []  272.63 232.86 0 top
NOREF#826  -  []  140.83 203.76 90 top
NOREF#827  -  []  189.67 190.01 0 top
NOREF#828  -  []  166.32 202.32 0 top
NOREF#829  -  []  185.41 226.99 90 top
NOREF#830  -  []  268.78 244.35 0 top
NOREF#831  -  []  129.05 232.28 0 top
NOREF#832  -  []  243.84 213.41 90 top
NOREF#833  -  []  187.8 265.39 90 top
NOREF#834  -  []  190.88 168.6 90 top
NOREF#835  -  []  251.21 234.24 90 top
NOREF#836  -  []  229.84 279.54 0 top
NOREF#837  -  []  279.44 179.15 0 top
NOREF#838  -  []  232.11 231.4 0 top
NOREF#839  -  []  203.84 207.82 90 top
NOREF#840  -  []  266.69 237.02 90 top
NOREF#841  -  []  251.05 232.28 90 top
NOREF#842  -  []  204.61 294.24 90 top
NOREF#843  -  []  259.55 180.49 90 top
NOREF#844  -  []  147.8 209.99 0 top
NOREF#845  -  []  243.97 204.45 90 top
NOREF#846  -  []  193.98 238.07 0 top
NOREF#847  -  []  240.13 456.29 0 top
NOREF#848  -  []  106.68 128.02 90 top
NOREF#849  -  []  245.38 226.23 0 top
NOREF#850  -  []  159.27 207.82 90 top
NOREF#851  -  []  203.92 289.94 0 top
NOREF#852  -  []  187.77 257.6 0 top
NOREF#853  -  []  150.77 223.79 90 top
NOREF#854  -  []  147.51 252.5 90 top
NOREF#855  -  []  279.4 264.45 90 top
NOREF#856  -  []  227.77 181.47 0 top
NOREF#857  -  []  189.84 284.11 0 top
NOREF#858  -  []  155.49 168.7 90 top
NOREF#859  -  []  281.44 184.35 0 top
NOREF#860  -  []  203.84 274.21 0 top
NOREF#861  -  []  277.37 240.3 90 top
NOREF#862  -  []  129.36 361.96 0 top
NOREF#863  -  []  265.61 197.6 0 top
NOREF#864  -  []  164.95 264.23 90 top
NOREF#865  -  []  202.85 237.22 0 top
NOREF#866  -  []  177.25 176.5 90 top
NOREF#867  -  []  140.04 265.53 90 top
NOREF#868  -  []  138.35 209.04 0 top
NOREF#869  -  []  235.92 250.88 90 top
NOREF#870  -  []  156.8 225.06 90 top
NOREF#871  -  []  148.78 222.65 0 top
NOREF#872  -  []  138.85 181.15 90 top
NOREF#873  -  []  262.87 226.99 0 top
NOREF#874  -  []  228.32 182.05 0 top
NOREF#875  -  []  168.54 207.5 90 top
NOREF#876  -  []  157.37 180.3 90 top
NOREF#877  -  []  283.52 83.81 0 top
NOREF#878  -  []  201.75 269.17 0 top
NOREF#879  -  []  235.49 228.7 90 top
NOREF#880  -  []  239.22 195.7 90 top
NOREF#881  -  []  240.11 18.69 0 top
NOREF#882  -  []  133.45 244.35 0 top
NOREF#883  -  []  276.8 225.06 90 top
NOREF#884  -  []  153.27 198.18 0 top
NOREF#885  -  []  180.59 244.98 90 top
NOREF#886  -  []  233.27 253.35 0 top
NOREF#887  -  []  196.81 232.54 0 top
NOREF#888  -  []  236.45 247.71 0 top
NOREF#889  -  []  253.45 244.35 0 top
NOREF#890  -  []  266.01 255.7 90 top
NOREF#891  -  []  132.55 190.49 90 top
NOREF#892  -  []  269.84 273.7 0 top
NOREF#893  -  []  272.11 231.4 0 top
NOREF#894  -  []  236.8 274.65 90 top
NOREF#895  -  []  236.52 216.55 0 top
NOREF#896  -  []  190.6 233.69 0 top
NOREF#897  -  []  243.84 260.97 90 top
NOREF#898  -  []  267.3 286.19 0 top
NOREF#899  -  []  146.83 251.93 0 top
NOREF#900  -  []  204.44 232.28 90 top
NOREF#901  -  []  192.25 222.59 90 top
NOREF#902  -  []  237.04 184.35 0 top
NOREF#903  -  []  131.05 232.28 90 top
NOREF#904  -  []  157.71 173.69 0 top
NOREF#905  -  []  195.05 218.82 0 top
NOREF#906  -  []  275.92 190.88 90 top
NOREF#907  -  []  195.05 223.39 0 top
NOREF#908  -  []  191.95 178.07 0 top
NOREF#909  -  []  239.27 267.82 90 top
NOREF#910  -  []  190.6 173.69 90 top
NOREF#911  -  []  173.24 201.55 0 top
NOREF#912  -  []  167.98 226.38 90 top
NOREF#913  -  []  214.09 260.42 90 top
NOREF#914  -  []  137.28 286.47 90 top
NOREF#915  -  []  236.38 181.15 90 top
NOREF#916  -  []  209.55 237.49 90 top
NOREF#917  -  []  150.41 168.7 90 top
NOREF#918  -  []  236.33 227.9 90 top
NOREF#919  -  []  232.13 284.66 0 top
NOREF#920  -  []  286.32 274.76 0 top
NOREF#921  -  []  275.68 233.69 90 top
NOREF#922  -  []  209.55 237.49 90 top
NOREF#923  -  []  138.56 246.51 0 top
NOREF#924  -  []  193.95 251.93 0 top
NOREF#925  -  []  181.55 267.14 90 top
NOREF#926  -  []  162.2 178.35 0 top
NOREF#927  -  []  174.09 264.23 90 top
NOREF#928  -  []  265.61 257.6 0 top
NOREF#929  -  []  158.64 233.37 90 top
NOREF#930  -  []  271.11 260.17 90 top
NOREF#931  -  []  227.43 284.11 90 top
NOREF#932  -  []  268.78 282.65 0 top
NOREF#933  -  []  224.04 245.96 0 top
NOREF#934  -  []  133.78 207.01 0 top
NOREF#935  -  []  251.25 244.35 0 top
NOREF#936  -  []  145.09 257.49 90 top
NOREF#937  -  []  278.91 232.21 90 top
NOREF#938  -  []  172.55 284.49 0 top
NOREF#939  -  []  189.72 281.62 0 top
NOREF#940  -  []  186.96 256.43 90 top
NOREF#941  -  []  279.24 184.35 0 top
NOREF#942  -  []  219.73 178.35 0 top
NOREF#943  -  []  243.84 265.58 0 top
NOREF#944  -  []  155.17 272.17 90 top
NOREF#945  -  []  227.8 204.99 90 top
NOREF#946  -  []  312.52 456.29 90 top
NOREF#947  -  []  243.84 205.58 0 top
NOREF#948  -  []  209.52 210.32 90 top
NOREF#949  -  []  277.18 176.17 90 top
NOREF#950  -  []  243.97 210.55 90 top
NOREF#951  -  []  249.17 291.95 0 top
NOREF#952  -  []  259.08 261.22 0 top
NOREF#953  -  []  174.43 232.23 0 top
NOREF#954  -  []  171.05 232.28 90 top
NOREF#955  -  []  196.8 280.49 90 top
NOREF#956  -  []  273.76 255.7 90 top
NOREF#957  -  []  266.83 196.75 0 top
NOREF#958  -  []  153.27 258.18 0 top
NOREF#959  -  []  187.43 218.27 0 top
NOREF#960  -  []  273.76 250.88 90 top
NOREF#961  -  []  122.44 292.28 0 top
NOREF#962  -  []  195.96 168.6 90 top
NOREF#963  -  []  203.1 18.69 90 top
NOREF#964  -  []  194.07 256.43 90 top
NOREF#965  -  []  192.63 233.69 0 top
NOREF#966  -  []  132.26 248.4 0 top
NOREF#967  -  []  199.4 267.5 90 top
NOREF#968  -  []  191.24 193.03 90 top
NOREF#969  -  []  203.97 205.9 0 top
NOREF#970  -  []  281.75 272.22 0 top
NOREF#971  -  []  156.84 227.33 0 top
NOREF#972  -  []  135.15 260.67 90 top
NOREF#973  -  []  149.72 281.62 0 top
NOREF#974  -  []  203.84 201.77 0 top
NOREF#975  -  []  148.24 392.33 90 top
NOREF#976  -  []  182.81 257.6 0 top
NOREF#977  -  []  265.42 214.72 90 top
NOREF#978  -  []  203.97 270.55 90 top
NOREF#979  -  []  185.41 213.02 90 top
NOREF#980  -  []  271.11 193.35 0 top
NOREF#981  -  []  196.52 285.69 0 top
NOREF#982  -  []  197.71 233.69 90 top
NOREF#983  -  []  246.32 266.13 0 top
NOREF#984  -  []  243.97 273.09 90 top
NOREF#985  -  []  172.87 287.4 90 top
NOREF#986  -  []  166.32 214.76 0 top
NOREF#987  -  []  175.11 261.22 90 top
NOREF#988  -  []  169.49 280.89 0 top
NOREF#989  -  []  294.09 267.27 90 top
NOREF#990  -  []  272.25 218.02 90 top
NOREF#991  -  []  263.49 257.85 90 top
NOREF#992  -  []  270.56 252.78 0 top
NOREF#993  -  []  136.5 271.94 0 top
NOREF#994  -  []  207.04 299.09 0 top
NOREF#995  -  []  184.04 245.96 0 top
NOREF#996  -  []  162.2 238.35 0 top
NOREF#997  -  []  146.28 253.03 90 top
NOREF#998  -  []  267.8 204.99 90 top
NOREF#999  -  []  193.18 222.26 90 top
NOREF#1000  -  []  148.35 277.95 90 top
NOREF#1001  -  []  132.87 287.4 90 top
NOREF#1002  -  []  171.05 245.49 90 top
NOREF#1003  -  []  267.43 284.11 0 top
NOREF#1004  -  []  189.84 273.7 0 top
NOREF#1005  -  []  191.53 173.37 90 top
NOREF#1006  -  []  153.83 232.21 90 top
NOREF#1007  -  []  176.55 194.49 90 top
NOREF#1008  -  []  150.56 192.78 0 top
NOREF#1009  -  []  266.69 223.05 90 top
NOREF#1010  -  []  248.42 204.78 90 top
NOREF#1011  -  []  189.84 279.54 0 top
NOREF#1012  -  []  150.56 197.6 0 top
NOREF#1013  -  []  216.26 263.76 90 top
NOREF#1014  -  []  168.42 265.58 0 top
NOREF#1015  -  []  218.85 241.15 90 top
NOREF#1016  -  []  270.77 213.37 90 top
NOREF#1017  -  []  116.51 14.59 90 top
NOREF#1018  -  []  195.17 281.32 0 top
NOREF#1019  -  []  226.16 193.35 0 top
NOREF#1020  -  []  236.57 182.05 0 top
NOREF#1021  -  []  251.21 234.89 90 top
NOREF#1022  -  []  258.95 201.55 0 top
NOREF#1023  -  []  149.67 247.68 90 top
NOREF#1024  -  []  277.25 196.75 0 top
NOREF#1025  -  []  195.58 202.67 90 top
NOREF#1026  -  []  199.4 200.64 90 top
NOREF#1027  -  []  270.41 228.7 90 top
NOREF#1028  -  []  131.05 289.49 0 top
NOREF#1029  -  []  179.73 238.35 0 top
NOREF#1030  -  []  169.52 207.27 90 top
NOREF#1031  -  []  276.57 242.05 0 top
NOREF#1032  -  []  88.44 106.3 90 top
NOREF#1033  -  []  250.89 266.13 0 top
NOREF#1034  -  []  253.36 261.22 0 top
NOREF#1035  -  []  220.83 208.59 90 top
NOREF#1036  -  []  231.19 218.07 0 top
NOREF#1037  -  []  141.03 207.69 90 top
NOREF#1038  -  []  231.11 200.17 90 top
NOREF#1039  -  []  156.1 220.99 90 top
NOREF#1040  -  []  218.35 211.84 0 top
NOREF#1041  -  []  143.36 253.35 0 top
NOREF#1042  -  []  286.32 206.13 0 top
NOREF#1043  -  []  272.25 272.17 90 top
NOREF#1044  -  []  171.25 184.35 0 top
NOREF#1045  -  []  197.37 191.6 90 top
NOREF#1046  -  []  173.64 239.09 0 top
NOREF#1047  -  []  276.52 276.55 0 top
NOREF#1048  -  []  134.43 232.23 0 top
NOREF#1049  -  []  237.25 191.93 0 top
NOREF#1050  -  []  136.55 194.49 90 top
NOREF#1051  -  []  192.25 282.59 90 top
NOREF#1052  -  []  169.52 200.42 90 top
NOREF#1053  -  []  229.12 191.6 90 top
NOREF#1054  -  []  211.05 292.28 90 top
NOREF#1055  -  []  168.42 207.82 90 top
NOREF#1056  -  []  188.78 184.35 0 top
NOREF#1057  -  []  233.6 216.55 0 top
NOREF#1058  -  []  168.54 267.5 90 top
NOREF#1059  -  []  156.57 242.05 0 top
NOREF#1060  -  []  266.96 191.6 90 top
NOREF#1061  -  []  156.57 193.35 0 top
NOREF#1062  -  []  260.83 205.79 90 top
NOREF#1063  -  []  228.19 247.71 0 top
NOREF#1064  -  []  140.95 268.91 90 top
NOREF#1065  -  []  196.57 242.05 0 top
NOREF#1066  -  []  276.38 181.15 90 top
NOREF#1067  -  []  136.5 285.91 90 top
NOREF#1068  -  []  187.99 178.35 0 top
NOREF#1069  -  []  279.72 274.65 90 top
NOREF#1070  -  []  260.83 265.79 90 top
NOREF#1071  -  []  205.38 286.23 0 top
NOREF#1072  -  []  191.87 456.29 0 top
NOREF#1073  -  []  271.46 167 0 top
NOREF#1074  -  []  162.2 238.35 0 top
NOREF#1075  -  []  154.63 279.22 90 top
NOREF#1076  -  []  192.66 226.35 90 top
NOREF#1077  -  []  206.32 214.76 0 top
NOREF#1078  -  []  133.45 184.35 0 top
NOREF#1079  -  []  148.95 266.89 0 top
NOREF#1080  -  []  267.8 265.39 90 top
NOREF#1081  -  []  168.42 268.62 0 top
NOREF#1082  -  []  236.57 245.63 0 top
NOREF#1083  -  []  264.16 251.6 90 top
NOREF#1084  -  []  159.27 214.21 0 top
NOREF#1085  -  []  243.97 264.45 90 top
NOREF#1086  -  []  124.32 231.95 90 top
NOREF#1087  -  []  281.44 244.35 0 top
NOREF#1088  -  []  277.71 173.69 0 top
NOREF#1089  -  []  140.95 266.12 90 top
NOREF#1090  -  []  173.65 239.15 0 top
NOREF#1091  -  []  191.98 286.59 90 top
NOREF#1092  -  []  183.49 253.03 90 top
NOREF#1093  -  []  228.44 257.85 90 top
NOREF#1094  -  []  279.27 274.21 0 top
NOREF#1095  -  []  149.84 213.7 90 top
NOREF#1096  -  []  243.97 214.54 0 top
NOREF#1097  -  []  299.62 18.69 90 top
NOREF#1098  -  []  197.59 235.77 0 top
NOREF#1099  -  []  260.83 208.59 90 top
NOREF#1100  -  []  154.07 251.6 90 top
NOREF#1101  -  []  208.42 201.77 0 top
NOREF#1102  -  []  153.6 222.39 0 top
NOREF#1103  -  []  219.55 294.49 0 top
NOREF#1104  -  []  236.81 172.54 0 top
NOREF#1105  -  []  268.35 217.95 90 top
NOREF#1106  -  []  269.67 190.01 0 top
